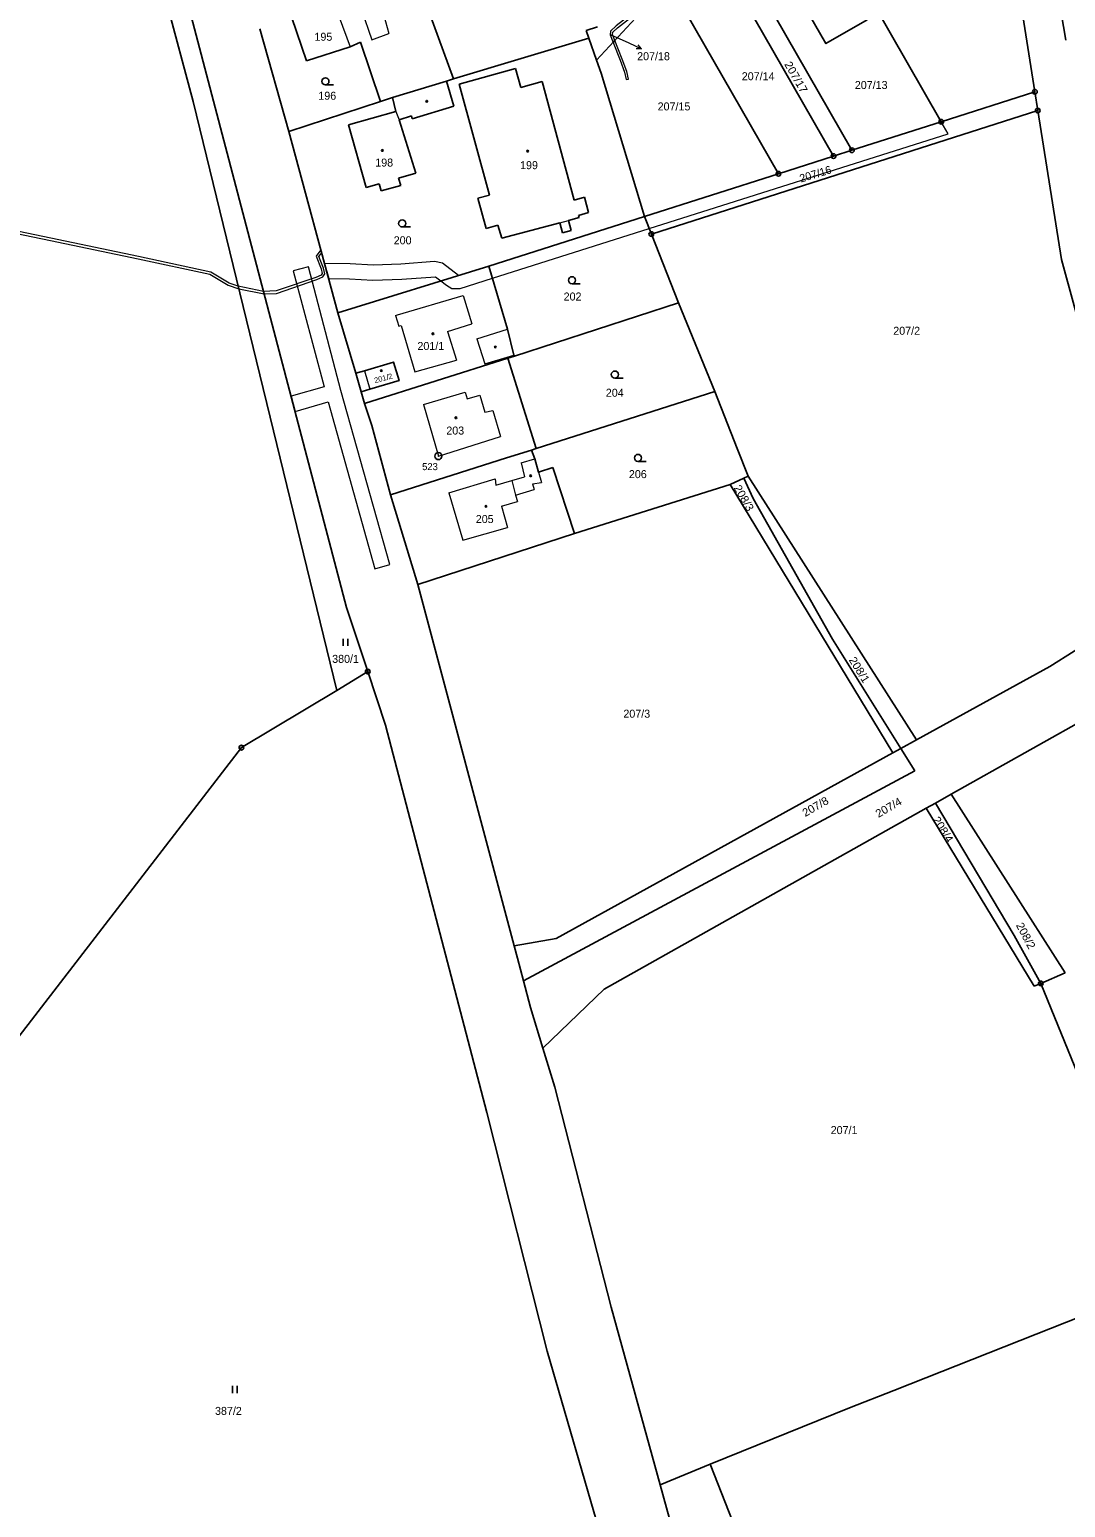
# Model space of a CAD drawing. Extents: x -633485 to -630509, y -1112692 to -1108818.
# Drawn here: x -631981.6 to -631761.6, y -1112246.7 to -1111932.7 of the extents above; entities that cross this region are included whole.
import ezdxf
from ezdxf.enums import TextEntityAlignment as Align

# ---------------------------------------------------------------- set-up
doc = ezdxf.new("R2010")
doc.units = 0
doc.header["$LTSCALE"] = 0.68
for name, color, linetype, lineweight in [('1', 7, 'Continuous', 25), ('13', 7, 'Continuous', 13), ('3', 7, 'Continuous', 25), ('4', 7, 'Continuous', 13), ('5', 7, 'Continuous', 25), ('7', 7, 'Continuous', 13), ('8', 7, 'Continuous', 25)]:
    doc.layers.add(name, color=color, linetype=linetype, lineweight=lineweight)
doc.layers.add('2', color=7, linetype='Continuous')

msp = doc.modelspace()

# ---------------------------------------------------------------- linework, layer by layer
at = {"layer": '1'}
for p, q in [((-631777.31, -1111887.62), (-631768.08, -1111945.95)), ((-631901.48, -1111915.84), (-631891.55, -1111943.23)), ((-631806.94, -1111958.37), (-631830.64, -1111917.06)), ((-631822.53, -1111963.35), (-631844.65, -1111924.8)), ((-631763.67, -1111922.15), (-631761.5, -1111934.97)), ((-631952.6, -1111926.6), (-631946.86, -1111947.99)), ((-631948.02, -1111926.89), (-631914.27, -1112055.54)), ((-631861.16, -1111939.24), (-631851.05, -1111928.33)), ((-631925.86, -1111930.24), (-631922.8, -1111939.4)), ((-631932.7, -1111932.56), (-631926.51, -1111954.39)), ((-631891.55, -1111943.23), (-631862.81, -1111934.52)), ((-631863.34, -1111932.89), (-631860.98, -1111932.17)), ((-631863.34, -1111932.89), (-631862.81, -1111934.52)), ((-631861.16, -1111939.24), (-631862.81, -1111934.52)), ((-631922.8, -1111939.4), (-631913.5, -1111936.43)), ((-631913.5, -1111936.43), (-631911.32, -1111935.41)), ((-631911.32, -1111935.41), (-631907.03, -1111948.04)), ((-631860.2, -1111942), (-631861.16, -1111939.24)), ((-631904.52, -1111947.16), (-631893.07, -1111943.69)), ((-631893.07, -1111943.69), (-631891.55, -1111943.23)), ((-631893.07, -1111943.69), (-631891.47, -1111948.98)), ((-631890.35, -1111944.32), (-631878.37, -1111941)), ((-631878.37, -1111941), (-631877.25, -1111945.01)), ((-631877.25, -1111945.01), (-631872.74, -1111943.75)), ((-631872.74, -1111943.75), (-631865.89, -1111968.95)), ((-631860.2, -1111942), (-631851, -1111972.44)), ((-631907.03, -1111948.04), (-631904.52, -1111947.16)), ((-631904.52, -1111947.16), (-631903.78, -1111950.11)), ((-631890.35, -1111944.32), (-631883.88, -1111967.9)), ((-631767.45, -1111949.95), (-631768.08, -1111945.95)), ((-631946.86, -1111947.99), (-631916.36, -1112073.13)), ((-631926.51, -1111954.39), (-631907.03, -1111948.04)), ((-631913.86, -1111952.98), (-631903.78, -1111950.11)), ((-631900.3, -1111951.66), (-631891.47, -1111948.98)), ((-631767.45, -1111949.95), (-631762.44, -1111981.58)), ((-631913.86, -1111952.98), (-631910.13, -1111966.25)), ((-631903.09, -1111951.88), (-631900.48, -1111951.09)), ((-631903.09, -1111951.88), (-631899.54, -1111963.27)), ((-631900.48, -1111951.09), (-631900.3, -1111951.66)), ((-631926.51, -1111954.39), (-631916.1, -1111992.92)), ((-631810.84, -1111959.61), (-631806.94, -1111958.37)), ((-631910.13, -1111966.25), (-631907.36, -1111965.47)), ((-631907.36, -1111965.47), (-631906.93, -1111967)), ((-631906.93, -1111967), (-631902.76, -1111965.88)), ((-631903.2, -1111964.3), (-631899.54, -1111963.27)), ((-631903.2, -1111964.3), (-631902.76, -1111965.88)), ((-631822.53, -1111963.35), (-631851, -1111972.44)), ((-631886.36, -1111968.56), (-631883.88, -1111967.9)), ((-631886.36, -1111968.56), (-631884.58, -1111974.97)), ((-631865.89, -1111968.95), (-631863.73, -1111968.36)), ((-631863.73, -1111968.36), (-631862.86, -1111971.56)), ((-631864.99, -1111972.25), (-631862.86, -1111971.56)), ((-631864.99, -1111972.25), (-631864.85, -1111972.69)), ((-631884.58, -1111974.97), (-631882.11, -1111974.28)), ((-631884.03, -1111982.99), (-631851, -1111972.44)), ((-631882.11, -1111974.28), (-631881.32, -1111977.08)), ((-631881.32, -1111977.08), (-631868.95, -1111973.78)), ((-631868.95, -1111973.78), (-631868.41, -1111975.89)), ((-631868.41, -1111975.89), (-631866.58, -1111975.41)), ((-631867.13, -1111973.3), (-631864.85, -1111972.69)), ((-631867.13, -1111973.3), (-631866.58, -1111975.41)), ((-631849.53, -1111976.17), (-631851, -1111972.44)), ((-631762.44, -1111981.58), (-631744.2, -1112048.41)), ((-631916.1, -1111992.92), (-631884.03, -1111982.99)), ((-631884.03, -1111982.99), (-631880.05, -1111996.36)), ((-631878.63, -1112002.12), (-631843.75, -1111990.79)), ((-631843.75, -1111990.79), (-631836.05, -1112009.66)), ((-631916.1, -1111992.92), (-631912.31, -1112005.76)), ((-631880.05, -1111996.36), (-631878.75, -1112001.94)), ((-631910.42, -1112012.17), (-631880.01, -1112002.55)), ((-631880.01, -1112002.55), (-631878.63, -1112002.12)), ((-631880.01, -1112002.55), (-631873.98, -1112021.71)), ((-631878.75, -1112001.94), (-631878.63, -1112002.12)), ((-631912.31, -1112005.76), (-631910.47, -1112005.22)), ((-631912.31, -1112005.76), (-631911.15, -1112009.68)), ((-631909.29, -1112009.13), (-631911.15, -1112009.68)), ((-631911.15, -1112009.68), (-631910.42, -1112012.17)), ((-631873.98, -1112021.71), (-631836.05, -1112009.66)), ((-631836.05, -1112009.66), (-631831.27, -1112021.74)), ((-631910.42, -1112012.17), (-631908.9, -1112016.82)), ((-631908.9, -1112016.82), (-631904.95, -1112031.57)), ((-631880.29, -1112023.72), (-631874.95, -1112022.08)), ((-631874.95, -1112022.08), (-631873.98, -1112021.71)), ((-631874.95, -1112022.08), (-631874.27, -1112023.9)), ((-631831.27, -1112021.74), (-631828.95, -1112027.6)), ((-631904.95, -1112031.57), (-631880.29, -1112023.72)), ((-631874.27, -1112023.9), (-631873.53, -1112026.75)), ((-631873.53, -1112026.75), (-631870.44, -1112025.78)), ((-631870.44, -1112025.78), (-631865.83, -1112039.78)), ((-631832.82, -1112029.41), (-631829.89, -1112028.04)), ((-631829.89, -1112028.04), (-631828.95, -1112027.6)), ((-631829.89, -1112028.04), (-631827.91, -1112032.38)), ((-631828.95, -1112027.6), (-631793.22, -1112083.66)), ((-631904.95, -1112031.57), (-631899.16, -1112050.61)), ((-631865.83, -1112039.78), (-631832.82, -1112029.41)), ((-631832.82, -1112029.41), (-631798.25, -1112086.43)), ((-631827.91, -1112032.38), (-631811.08, -1112062.28)), ((-631899.16, -1112050.61), (-631865.83, -1112039.78)), ((-631899.16, -1112050.61), (-631878.68, -1112127.42)), ((-631914.27, -1112055.54), (-631909.75, -1112069.15)), ((-631811.08, -1112062.28), (-631796.57, -1112085.5)), ((-631764.9, -1112068.05), (-631753.62, -1112060.89)), ((-631916.36, -1112073.13), (-631909.75, -1112069.15)), ((-631909.75, -1112069.15), (-631905.98, -1112080.51)), ((-631793.22, -1112083.66), (-631764.9, -1112068.05)), ((-631936.6, -1112085.3), (-631916.36, -1112073.13)), ((-631785.86, -1112095.2), (-631750.38, -1112075.25)), ((-631905.98, -1112080.51), (-631884.49, -1112162.81)), ((-632035.8, -1112214.11), (-631936.6, -1112085.3)), ((-631796.57, -1112085.5), (-631793.22, -1112083.66)), ((-631869.76, -1112125.84), (-631798.25, -1112086.43)), ((-631798.25, -1112086.43), (-631796.57, -1112085.5)), ((-631796.57, -1112085.5), (-631793.58, -1112090.2)), ((-631876.69, -1112134.85), (-631793.58, -1112090.2)), ((-631791.14, -1112098.17), (-631789.19, -1112097.07)), ((-631789.19, -1112097.07), (-631785.86, -1112095.2)), ((-631789.19, -1112097.07), (-631772.5, -1112125.18)), ((-631785.86, -1112095.2), (-631761.67, -1112133.15)), ((-631859.56, -1112136.63), (-631791.14, -1112098.17)), ((-631791.14, -1112098.17), (-631768.21, -1112136)), ((-631878.68, -1112127.42), (-631869.76, -1112125.84)), ((-631766.84, -1112135.4), (-631772.5, -1112125.18)), ((-631878.68, -1112127.42), (-631877.98, -1112130.02)), ((-631877.98, -1112130.02), (-631876.69, -1112134.85)), ((-631876.69, -1112134.85), (-631875.18, -1112140.53)), ((-631768.21, -1112136), (-631766.84, -1112135.4)), ((-631766.84, -1112135.4), (-631761.67, -1112133.15)), ((-631766.84, -1112135.4), (-631728.62, -1112229.26)), ((-631872.56, -1112149.16), (-631859.56, -1112136.63)), ((-631875.18, -1112140.53), (-631872.56, -1112149.16)), ((-631872.56, -1112149.16), (-631870.05, -1112157.42)), ((-631870.05, -1112157.42), (-631858.07, -1112204.21)), ((-631884.49, -1112162.81), (-631871.65, -1112213.51)), ((-631798.01, -1112221.88), (-631745.69, -1112201.18)), ((-631858.07, -1112204.21), (-631847.63, -1112241.93)), ((-631871.65, -1112213.51), (-631852.59, -1112278.99)), ((-631807.44, -1112225.59), (-631798.01, -1112221.88)), ((-631837.04, -1112237.53), (-631807.44, -1112225.59)), ((-631847.63, -1112241.93), (-631837.04, -1112237.53)), ((-631837.04, -1112237.53), (-631803.82, -1112321.88)), ((-631847.63, -1112241.93), (-631840.88, -1112266.32))]:
    msp.add_line(p, q, dxfattribs=at)
for points in [[(-631787.95, -1111952.3), (-631813.56, -1111907.63), (-631777.31, -1111887.62)], [(-631811.7, -1111916.74), (-631803.71, -1111930.68), (-631812.47, -1111935.7), (-631820.46, -1111921.76)], [(-631834.14, -1111918.99), (-631810.84, -1111959.61), (-631822.53, -1111963.35)], [(-631768.08, -1111945.95), (-631787.95, -1111952.3), (-631806.94, -1111958.37)], [(-631843.75, -1111990.79), (-631849.53, -1111976.17), (-631767.45, -1111949.95)], [(-631910.47, -1112005.22), (-631904.28, -1112003.39), (-631903.12, -1112007.32), (-631909.29, -1112009.13)]]:
    msp.add_lwpolyline(points, dxfattribs=at)
at = {"layer": '13'}
for points in [[(-631857.66, -1111935.46), (-631857.28, -1111935.05), (-631857.77, -1111933.81), (-631857.73, -1111933.31), (-631856.7, -1111932.34), (-631852, -1111928.7), (-631853.64, -1111929.33), (-631857.02, -1111931.96), (-631858.21, -1111933.07), (-631858.29, -1111933.87)], [(-631857.66, -1111935.46), (-631856.16, -1111939.23), (-631855.22, -1111941.79), (-631854.86, -1111943.35), (-631854.37, -1111943.24), (-631854.74, -1111941.65), (-631855.7, -1111939.03), (-631857.28, -1111935.05)], [(-631890.16, -1111987.74), (-631883.26, -1111985.56), (-631849.98, -1111975.03), (-631786.47, -1111954.88), (-631787.95, -1111952.3), (-631806.94, -1111958.37), (-631810.84, -1111959.61), (-631822.53, -1111963.35), (-631851, -1111972.44), (-631884.03, -1111982.99), (-631890.49, -1111984.99), (-631893.88, -1111982.33), (-631895.59, -1111982.04), (-631902.74, -1111982.55), (-631908.63, -1111982.78), (-631913.52, -1111982.5), (-631918.93, -1111982.44), (-631918.06, -1111985.65), (-631913.62, -1111985.7), (-631908.65, -1111985.98), (-631902.56, -1111985.75), (-631895.36, -1111985.24), (-631894.21, -1111986.14), (-631893.04, -1111987.05), (-631891.93, -1111987.71)], [(-631931.88, -1111988.41), (-631931.75, -1111988.9), (-631929.14, -1111988.77), (-631920.58, -1111985.86), (-631919.27, -1111985.26), (-631918.9, -1111984.62), (-631919.16, -1111983.39), (-631920.15, -1111980.92), (-631919.55, -1111980.15), (-631919.71, -1111979.56), (-631920.73, -1111980.84), (-631919.64, -1111983.53), (-631919.42, -1111984.54), (-631919.63, -1111984.88), (-631920.76, -1111985.4), (-631929.24, -1111988.27)], [(-631915.45, -1112009.38), (-631922.38, -1111983.14), (-631925.57, -1111983.98), (-631919.05, -1112008.65), (-631926.05, -1112010.64), (-631925.21, -1112013.85), (-631918.18, -1112011.84), (-631908.28, -1112047.28), (-631905.1, -1112046.4)]]:
    msp.add_lwpolyline(points, close=True, dxfattribs=at)
msp.add_lwpolyline([(-632008.55, -1111971.02), (-631977.14, -1111977.54), (-631958.54, -1111981.41), (-631943.29, -1111984.72), (-631939.43, -1111987.07), (-631937.16, -1111987.79), (-631931.75, -1111988.9), (-631931.88, -1111988.41), (-631937.3, -1111987.23), (-631939.23, -1111986.61), (-631943.11, -1111984.24), (-631958.44, -1111980.93), (-631977.04, -1111977.06), (-632008.45, -1111970.54)], dxfattribs=at)
at = {"layer": '3'}
for p, q in [((-631918.753, -1111944.48), (-631917.003, -1111944.48)), ((-631902.453, -1111974.67), (-631900.703, -1111974.67)), ((-631866.383, -1111986.74), (-631864.633, -1111986.74)), ((-631857.283, -1112006.78), (-631855.533, -1112006.78)), ((-631852.383, -1112024.48), (-631850.633, -1112024.48)), ((-631915.001, -1112063.68), (-631915.001, -1112062.18)), ((-631914, -1112063.68), (-631914, -1112062.18)), ((-631938.491, -1112222.43), (-631938.491, -1112220.93)), ((-631937.49, -1112222.43), (-631937.49, -1112220.93))]:
    msp.add_line(p, q, dxfattribs=at)
for centre in [(-631918.7529, -1111943.7298), (-631902.4529, -1111973.9198), (-631866.3829, -1111985.9898), (-631857.2829, -1112006.0298), (-631852.3829, -1112023.7298)]:
    msp.add_circle(centre, 0.75, dxfattribs=at)
at = {"layer": '4'}
for p, q in [((-631907.85, -1111924.27), (-631905.28, -1111933.59)), ((-631915.87, -1111930.08), (-631913.5, -1111936.43)), ((-631911.11, -1111928.56), (-631908.89, -1111934.89)), ((-631908.89, -1111934.89), (-631905.28, -1111933.59)), ((-631903.78, -1111950.11), (-631903.09, -1111951.88)), ((-631868.95, -1111973.78), (-631867.13, -1111973.3)), ((-631903.41, -1111993.34), (-631889.49, -1111989.25)), ((-631889.49, -1111989.25), (-631887.64, -1111995.25)), ((-631903.89, -1111993.48), (-631903.41, -1111993.34)), ((-631903.89, -1111993.48), (-631903.13, -1111995.74)), ((-631903.13, -1111995.74), (-631902.7, -1111995.6)), ((-631902.7, -1111995.6), (-631899.79, -1112005.48)), ((-631892.84, -1111996.9), (-631887.64, -1111995.25)), ((-631892.84, -1111996.9), (-631890.89, -1112002.99)), ((-631886.59, -1111998.41), (-631880.05, -1111996.36)), ((-631886.59, -1111998.41), (-631884.91, -1112003.78)), ((-631899.79, -1112005.48), (-631890.89, -1112002.99)), ((-631884.91, -1112003.78), (-631878.75, -1112001.94)), ((-631910.47, -1112005.22), (-631909.29, -1112009.13)), ((-631897.93, -1112012.36), (-631889.05, -1112009.8)), ((-631889.05, -1112009.8), (-631888.64, -1112011.22)), ((-631897.93, -1112012.36), (-631894.76, -1112023.36)), ((-631888.64, -1112011.22), (-631885.93, -1112010.44)), ((-631885.93, -1112010.44), (-631884.9, -1112014.01)), ((-631884.9, -1112014.01), (-631883.19, -1112013.63)), ((-631883.19, -1112013.63), (-631881.58, -1112019.2)), ((-631894.76, -1112023.36), (-631881.58, -1112019.2)), ((-631877.16, -1112024.79), (-631874.27, -1112023.9)), ((-631877.16, -1112024.79), (-631876.45, -1112027.76)), ((-631892.51, -1112031.16), (-631882.68, -1112028.15)), ((-631882.68, -1112028.15), (-631882.57, -1112029.53)), ((-631882.57, -1112029.53), (-631879.15, -1112028.54)), ((-631879.15, -1112028.54), (-631876.45, -1112027.76)), ((-631879.15, -1112028.54), (-631878.36, -1112031.63)), ((-631873.53, -1112026.75), (-631872.88, -1112028.98)), ((-631892.51, -1112031.16), (-631889.59, -1112041.25)), ((-631878.36, -1112031.63), (-631874.39, -1112030.48)), ((-631878.36, -1112031.63), (-631877.95, -1112033.01)), ((-631874.75, -1112029.22), (-631872.88, -1112028.98)), ((-631874.75, -1112029.22), (-631874.39, -1112030.48)), ((-631881.38, -1112034), (-631877.95, -1112033.01)), ((-631881.38, -1112034), (-631880.08, -1112038.5)), ((-631889.59, -1112041.25), (-631880.08, -1112038.5))]:
    msp.add_line(p, q, dxfattribs=at)
at = {"layer": '5'}
for centre in [(-631897.2268, -1111947.9592), (-631906.6768, -1111958.4192), (-631875.7868, -1111958.5492), (-631895.9268, -1111997.3592), (-631882.6668, -1112000.1892), (-631906.8868, -1112005.1892), (-631891.0468, -1112015.2192), (-631875.1468, -1112027.5392), (-631884.6468, -1112034.0092)]:
    msp.add_circle(centre, 0.175, dxfattribs=at)
at = {"layer": '7'}
msp.add_line((-631851.62, -1111936.818), (-631852.316, -1111935.941), dxfattribs=at)
msp.add_lwpolyline([(-631858.25, -1111933.76), (-631854.34, -1111935.55), (-631851.62, -1111936.818), (-631852.739, -1111936.849)], dxfattribs=at)
at = {"layer": '8'}
for centre, radius in [((-631768.08, -1111945.9499), 0.5), ((-631768.08, -1111945.9499), 0.0303), ((-631767.45, -1111949.9499), 0.5), ((-631767.45, -1111949.9499), 0.0303), ((-631787.95, -1111952.2999), 0.5), ((-631787.95, -1111952.2999), 0.0303), ((-631810.84, -1111959.6099), 0.5), ((-631810.84, -1111959.6099), 0.0303), ((-631806.94, -1111958.3699), 0.5), ((-631806.94, -1111958.3699), 0.0303), ((-631822.53, -1111963.3499), 0.5), ((-631822.53, -1111963.3499), 0.0303), ((-631849.53, -1111976.1699), 0.5), ((-631849.53, -1111976.1699), 0.0303), ((-631894.76, -1112023.3598), 0.75), ((-631894.76, -1112023.3598), 0.03), ((-631909.75, -1112069.1499), 0.5), ((-631909.75, -1112069.1499), 0.0303), ((-631936.6, -1112085.2999), 0.5), ((-631936.6, -1112085.2999), 0.0303), ((-631766.84, -1112135.3999), 0.5), ((-631766.84, -1112135.3999), 0.0303)]:
    msp.add_circle(centre, radius, dxfattribs=at)

# ---------------------------------------------------------------- texts
at = {"layer": '2'}
for s, p in [('195', (-631921.08, -1111935.105)), ('196', (-631920.26, -1111947.635)), ('198', (-631908.17, -1111961.835)), ('199', (-631877.41, -1111962.385)), ('200', (-631904.25, -1111978.355)), ('202', (-631868.16, -1111990.295)), ('207/2', (-631798.15, -1111997.575)), ('204', (-631859.2, -1112010.745)), ('203', (-631893.08, -1112018.775)), ('206', (-631854.3, -1112028.035)), ('205', (-631886.82, -1112037.575)), ('380/1', (-631917.32, -1112067.285)), ('207/3', (-631855.47, -1112078.935)), ('207/1', (-631811.44, -1112167.405)), ('387/2', (-631942.2, -1112227.075))]:
    msp.add_text(s, height=1.7, dxfattribs=at).set_placement(p)
for s, p in [('207/18', (-631849.07, -1111939.235)), ('207/14', (-631826.85, -1111943.495)), ('207/13', (-631802.84, -1111945.355)), ('207/15', (-631844.72, -1111949.905)), ('201/1', (-631896.37, -1112000.815))]:
    msp.add_text(s, height=1.7, dxfattribs=at).set_placement(p, align=Align.CENTER)
at = {"layer": '2', "width": 1.05}
msp.add_text('207/17', height=1.7, rotation=300, dxfattribs=at).set_placement((-631819.5331, -1111943.258), align=Align.CENTER)
at = {"layer": '2'}
for s, height, rotation, p in [('207/16', 1.7, 17, (-631814.4285, -1111964.2268)), ('201/2', 1.139, 15, (-631906.3104, -1112007.3541))]:
    msp.add_text(s, height=height, rotation=rotation, dxfattribs=at).set_placement(p, align=Align.CENTER)
at = {"layer": '2', "width": 1.05}
for s, rotation, p in [('208/3', 300, (-631832.098, -1112030.082)), ('208/1', 302, (-631807.66, -1112066.665)), ('207/8', 30, (-631816.857, -1112100.058)), ('207/4', 30, (-631801.307, -1112100.238)), ('208/4', 302, (-631789.88, -1112100.595)), ('208/2', 298, (-631772.155, -1112123.019))]:
    msp.add_text(s, height=1.7, rotation=rotation, dxfattribs=at).set_placement(p)
at = {"layer": '8'}
msp.add_text('523', height=1.5, dxfattribs=at).set_placement((-631898.22, -1112026.335))

doc.saveas('drawing.dxf')
